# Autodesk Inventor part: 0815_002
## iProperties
Shininess: 64.0
Length Units: 11269
Angle Units: 11279
Time Units: 11290
Mass Units: 11283
Length Display Precision: 3
Angle Display Precision: 2
Compacted: True
Part Number: 0815_002
Document SubType Name: Modeling
Created: 2004-08
Material: Standard
Designer: P. Frank
Manufacturer: Standard
Standards Organization: Custom
Cost Center: 0 kg
Authority: 2587,51 mm^3
Density: 0.0
Volumn: 0.0
Area: 0.0
PropertySet Name: Model Information
Control State: 0
Master: False
Checked Out: False
SaveDate: 2004-08-15
SaveTime: 16:07
TotalMass: 0 kg
TotalVolume: 2587,51 mm^3
Author: P. Frank
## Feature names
1. Extrusion1
2. Extrusion2
3. Extrusion3
4. Extrusion4
5. Sweeping1
6. Trennen1
7. Trennen2
